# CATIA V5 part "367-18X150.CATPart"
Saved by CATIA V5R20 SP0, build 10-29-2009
Part number: 367-18X150
Definition: NONE
Nomenclature: 367-18X150
Source: Unknown
Description: 367-18X150
Bounding box of the stored display mesh (mm): x 0 to 150, y -14 to 14, z -14 to 14
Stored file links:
  C:\Users\Utente\Desktop\IO LAVORO\3D X SITO CF\X SITO\PLASTICA\3D files 367\367-18X150.CATPart
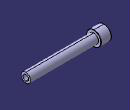
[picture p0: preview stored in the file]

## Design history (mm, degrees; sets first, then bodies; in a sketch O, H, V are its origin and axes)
Body1 "367-18X150" (main body)
  Solid1: solid without history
